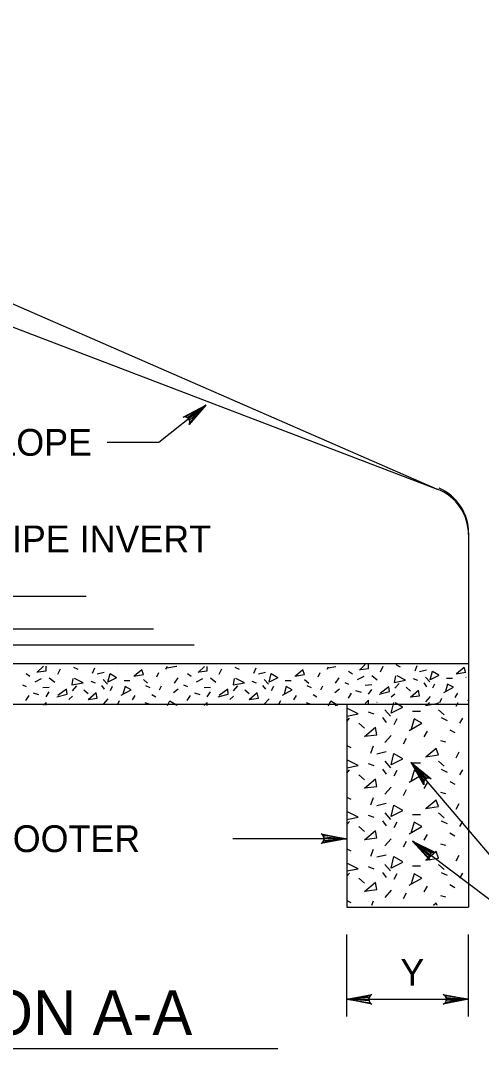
# Model space of a CAD drawing. Extents: x 1 to 8.2, y -2.1 to 8.1.
# Drawn here: x 3.034 to 4.066, y 2.836 to 5.137 of the extents above; entities that cross this region are included whole.
import ezdxf

# ---------------------------------------------------------------- set-up
doc = ezdxf.new("R2010")
doc.units = 0
for name, color, linetype in [('DETL-DIMS', 7, 'Continuous'), ('DETL-LINE', 7, 'Continuous'), ('DETL-NOTE', 7, 'Continuous'), ('DETL-PATT', 7, 'Continuous'), ('DETL-TITL', 7, 'Continuous')]:
    doc.layers.add(name, color=color, linetype=linetype)

msp = doc.modelspace()

# ---------------------------------------------------------------- linework, layer by layer
at = {"layer": 'DETL-DIMS'}
for p, q in [((3.4486, 4.2766), (3.3436, 4.1931)), ((3.3436, 4.1931), (3.2278, 4.1931)), ((4.3231, 2.9891), (3.9085, 3.4763)), ((3.763, 3.3059), (3.5089, 3.3059)), ((3.9112, 3.3004), (4.3231, 2.9891)), ((3.7642, 2.9079), (3.7642, 3.0918)), ((4.0369, 2.9079), (4.0369, 3.0918)), ((3.7642, 2.9464), (4.0369, 2.9464))]:
    msp.add_line(p, q, dxfattribs=at)
for points in [[(3.4486, 4.2766), (3.411, 4.2332), (3.4125, 4.2382), (3.4119, 4.2426), (3.4101, 4.246), (3.4072, 4.2485), (3.4031, 4.2501), (3.3978, 4.2498), (3.4486, 4.2766), (3.4031, 4.2501), (3.4072, 4.2485), (3.4486, 4.2766), (3.4101, 4.246), (3.4119, 4.2426), (3.4486, 4.2766), (3.4125, 4.2382)], [(3.9085, 3.4763), (3.9532, 3.4401), (3.9481, 3.4415), (3.9437, 3.4408), (3.9404, 3.4388), (3.9379, 3.4358), (3.9365, 3.4317), (3.937, 3.4264), (3.9085, 3.4763), (3.9365, 3.4317), (3.9379, 3.4358), (3.9085, 3.4763), (3.9404, 3.4388), (3.9437, 3.4408), (3.9085, 3.4763), (3.9481, 3.4415)], [(3.9085, 3.4763), (3.9532, 3.4401), (3.9481, 3.4415), (3.9437, 3.4408), (3.9404, 3.4388), (3.9379, 3.4358), (3.9365, 3.4317), (3.937, 3.4264), (3.9085, 3.4763), (3.9365, 3.4317), (3.9379, 3.4358), (3.9085, 3.4763), (3.9404, 3.4388), (3.9437, 3.4408), (3.9085, 3.4763), (3.9481, 3.4415)], [(3.763, 3.3059), (3.7065, 3.2954), (3.7108, 3.2984), (3.7131, 3.3022), (3.7137, 3.3059), (3.7131, 3.3097), (3.7108, 3.3135), (3.7065, 3.3165), (3.763, 3.3059), (3.7108, 3.3135), (3.7131, 3.3097), (3.763, 3.3059), (3.7137, 3.3059), (3.7131, 3.3022), (3.763, 3.3059), (3.7108, 3.2984)], [(3.9112, 3.3004), (3.9626, 3.2748), (3.9573, 3.275), (3.9533, 3.2733), (3.9505, 3.2707), (3.9487, 3.2673), (3.9482, 3.2629), (3.9499, 3.2579), (3.9112, 3.3004), (3.9482, 3.2629), (3.9487, 3.2673), (3.9112, 3.3004), (3.9505, 3.2707), (3.9533, 3.2733), (3.9112, 3.3004), (3.9573, 3.275)], [(3.7642, 2.9464), (3.8207, 2.9569), (3.8163, 2.9539), (3.8141, 2.9501), (3.8134, 2.9464), (3.8141, 2.9426), (3.8163, 2.9388), (3.8207, 2.9358), (3.7642, 2.9464), (3.8163, 2.9388), (3.8141, 2.9426), (3.7642, 2.9464), (3.8134, 2.9464), (3.8141, 2.9501), (3.7642, 2.9464), (3.8163, 2.9539)], [(4.0369, 2.9464), (3.9804, 2.9358), (3.9848, 2.9388), (3.987, 2.9426), (3.9877, 2.9464), (3.987, 2.9501), (3.9848, 2.9539), (3.9804, 2.9569), (4.0369, 2.9464), (3.9848, 2.9539), (3.987, 2.9501), (4.0369, 2.9464), (3.9877, 2.9464), (3.987, 2.9426), (4.0369, 2.9464), (3.9848, 2.9388)]]:
    msp.add_lwpolyline(points, dxfattribs=at)
at = {"layer": 'DETL-LINE'}
for p, q in [((1.5635, 5.1374), (3.9667, 4.0886)), ((2.3702, 4.6982), (3.9667, 4.0886)), ((4.0369, 3.9904), (4.0369, 3.6982)), ((1.5824, 3.8486), (3.1805, 3.8486)), ((1.5824, 3.7759), (3.3316, 3.7759)), ((1.5824, 3.7395), (3.4222, 3.7395)), ((1.6733, 3.6982), (4.0369, 3.6982)), ((4.0369, 3.6982), (4.0369, 3.1528)), ((1.5824, 3.6073), (4.0369, 3.6073)), ((3.7642, 3.6073), (3.7642, 3.1528)), ((3.7642, 3.1528), (4.0369, 3.1528))]:
    msp.add_line(p, q, dxfattribs=at)
for centre, end in [((3.9278, 3.9867), 69.1021), ((3.9278, 3.9904), 66.4251)]:
    msp.add_arc(centre, 0.1091, 0, end, dxfattribs=at)
at = {"layer": 'DETL-PATT'}
for p, q in [((3.0852, 3.6918), (3.0704, 3.6779)), ((3.1173, 3.6743), (3.1233, 3.6864)), ((3.1522, 3.69), (3.1619, 3.6852)), ((3.1992, 3.6876), (3.1943, 3.6755)), ((3.2499, 3.6915), (3.2497, 3.6912)), ((3.3592, 3.6852), (3.3625, 3.6912)), ((3.3832, 3.6912), (3.3616, 3.6876)), ((3.3832, 3.6912), (3.3832, 3.6912)), ((3.3832, 3.6912), (3.3832, 3.6912)), ((3.3832, 3.6912), (3.3832, 3.6912)), ((3.3832, 3.6912), (3.3832, 3.6912)), ((3.3832, 3.6912), (3.3832, 3.6912)), ((3.3832, 3.6912), (3.3832, 3.6912)), ((3.3832, 3.6912), (3.3832, 3.6912)), ((3.3832, 3.6912), (3.3832, 3.6912)), ((3.3832, 3.6912), (3.3832, 3.6912)), ((3.3832, 3.6912), (3.3832, 3.6912)), ((3.3832, 3.6912), (3.3832, 3.6912)), ((3.3832, 3.6912), (3.3832, 3.6912)), ((3.3833, 3.6912), (3.3832, 3.6912)), ((3.3833, 3.6912), (3.3833, 3.6912)), ((3.3833, 3.6912), (3.3833, 3.6912)), ((3.3833, 3.6912), (3.3833, 3.6912)), ((3.3833, 3.6912), (3.3833, 3.6912)), ((3.3833, 3.6912), (3.3833, 3.6912)), ((3.3833, 3.6912), (3.3833, 3.6912)), ((3.4453, 3.691), (3.4314, 3.6779)), ((3.4784, 3.6743), (3.4844, 3.6864)), ((3.5133, 3.69), (3.5229, 3.6852)), ((3.5602, 3.6876), (3.5554, 3.6755)), ((3.7203, 3.6852), (3.7231, 3.6904)), ((3.7395, 3.6904), (3.7227, 3.6876)), ((3.8055, 3.6957), (3.7925, 3.6834)), ((3.8394, 3.6798), (3.8454, 3.6919)), ((3.8743, 3.6955), (3.8839, 3.6906)), ((3.9212, 3.6931), (3.9164, 3.681)), ((3.9429, 3.6834), (3.9272, 3.6798)), ((3.0463, 3.6755), (3.0548, 3.6695)), ((3.08, 3.6635), (3.0656, 3.6563)), ((3.0981, 3.6659), (3.1101, 3.6563)), ((3.1907, 3.6587), (3.2004, 3.6551)), ((3.2208, 3.6779), (3.2052, 3.6743)), ((3.2184, 3.6623), (3.228, 3.6515)), ((3.2654, 3.6599), (3.2786, 3.6599)), ((3.3087, 3.6623), (3.3183, 3.6539)), ((3.3388, 3.6683), (3.3436, 3.6779)), ((3.3857, 3.6659), (3.3773, 3.6539)), ((3.4074, 3.6755), (3.4158, 3.6695)), ((3.4411, 3.6635), (3.4266, 3.6563)), ((3.4591, 3.6659), (3.4711, 3.6563)), ((3.5518, 3.6587), (3.5614, 3.6551)), ((3.5819, 3.6779), (3.5662, 3.6743)), ((3.5795, 3.6623), (3.5891, 3.6515)), ((3.6264, 3.6599), (3.6396, 3.6599)), ((3.6697, 3.6623), (3.6793, 3.6539)), ((3.6998, 3.6683), (3.7046, 3.6779)), ((3.7467, 3.6659), (3.7383, 3.6539)), ((3.7684, 3.681), (3.7768, 3.675)), ((3.8021, 3.669), (3.7876, 3.6618)), ((3.8201, 3.6714), (3.8322, 3.6618)), ((3.9128, 3.6642), (3.9224, 3.6606)), ((3.9405, 3.6678), (3.9501, 3.657)), ((3.9874, 3.6654), (4.0007, 3.6654)), ((4.0091, 3.675), (4.0305, 3.6786)), ((4.0307, 3.6678), (4.0316, 3.667)), ((3.0379, 3.6503), (3.0463, 3.6466)), ((3.0836, 3.6442), (3.0981, 3.6454)), ((3.1498, 3.637), (3.1595, 3.6479)), ((3.1751, 3.6394), (3.1847, 3.631)), ((3.2148, 3.6491), (3.2208, 3.6406)), ((3.2389, 3.6466), (3.2341, 3.637)), ((3.3135, 3.6491), (3.3231, 3.6442)), ((3.3448, 3.6394), (3.3496, 3.6479)), ((3.3869, 3.6406), (3.3761, 3.6322)), ((3.3989, 3.6503), (3.4074, 3.6466)), ((3.4447, 3.6442), (3.4591, 3.6454)), ((3.5109, 3.637), (3.5205, 3.6479)), ((3.5361, 3.6394), (3.5458, 3.631)), ((3.5758, 3.6491), (3.5819, 3.6406)), ((3.5999, 3.6466), (3.5951, 3.637)), ((3.6745, 3.6491), (3.6841, 3.6442)), ((3.7058, 3.6394), (3.7106, 3.6479)), ((3.7479, 3.6406), (3.7371, 3.6322)), ((3.76, 3.6557), (3.7684, 3.6521)), ((3.784, 3.6377), (3.7961, 3.6341)), ((3.8057, 3.6497), (3.8201, 3.6509)), ((3.8129, 3.6293), (3.8201, 3.6401)), ((3.8719, 3.6425), (3.8815, 3.6533)), ((3.8972, 3.6449), (3.9068, 3.6365)), ((3.9369, 3.6545), (3.9429, 3.6461)), ((3.9609, 3.6521), (3.9561, 3.6425)), ((3.0523, 3.6262), (3.0451, 3.6154)), ((3.062, 3.6322), (3.074, 3.6286)), ((3.0909, 3.6238), (3.0981, 3.6346)), ((3.1414, 3.6178), (3.1498, 3.625)), ((3.2292, 3.619), (3.2184, 3.6069)), ((3.2545, 3.6142), (3.2497, 3.6046)), ((3.2846, 3.6166), (3.2906, 3.6262)), ((3.3279, 3.6286), (3.3364, 3.6238)), ((3.4134, 3.6262), (3.4062, 3.6154)), ((3.423, 3.6322), (3.435, 3.6286)), ((3.4519, 3.6238), (3.4591, 3.6346)), ((3.5024, 3.6178), (3.5109, 3.625)), ((3.5903, 3.619), (3.5795, 3.6069)), ((3.6156, 3.6142), (3.6107, 3.6045)), ((3.6456, 3.6166), (3.6517, 3.6262)), ((3.689, 3.6286), (3.6974, 3.6238)), ((3.7744, 3.6317), (3.7672, 3.6208)), ((3.8635, 3.6233), (3.8719, 3.6305)), ((3.9513, 3.6245), (3.9405, 3.6124)), ((3.9766, 3.6196), (3.9718, 3.61)), ((4.0067, 3.6221), (4.0127, 3.6317)), ((4.0344, 3.616), (4.0363, 3.6155)), ((3.3123, 3.6105), (3.3207, 3.6081)), ((3.382, 3.6043), (3.3819, 3.6043)), ((3.3819, 3.6043), (3.3819, 3.6043)), ((3.3819, 3.6043), (3.3819, 3.6043)), ((3.3819, 3.6043), (3.3819, 3.6043)), ((3.3819, 3.6043), (3.3819, 3.6043)), ((3.3819, 3.6043), (3.3819, 3.6043)), ((3.3819, 3.6043), (3.3819, 3.6043)), ((3.3819, 3.6043), (3.3819, 3.6043)), ((3.3819, 3.6043), (3.3819, 3.6043)), ((3.3819, 3.6043), (3.3819, 3.6043)), ((3.3819, 3.6043), (3.3819, 3.6043)), ((3.3819, 3.6043), (3.3819, 3.6043)), ((3.3819, 3.6043), (3.3819, 3.6043)), ((3.3819, 3.6043), (3.3819, 3.6043)), ((3.3819, 3.6043), (3.3819, 3.6043)), ((3.3819, 3.6043), (3.3819, 3.6043)), ((3.3819, 3.6043), (3.3819, 3.6043)), ((3.3819, 3.6043), (3.3819, 3.6043)), ((3.3819, 3.6043), (3.3819, 3.6043)), ((3.3819, 3.6043), (3.3819, 3.6043)), ((3.3819, 3.6043), (3.3819, 3.6043)), ((3.3819, 3.6043), (3.3819, 3.6043)), ((3.3819, 3.6043), (3.3819, 3.6043)), ((3.3819, 3.6043), (3.3819, 3.6043)), ((3.3819, 3.6043), (3.3819, 3.6043)), ((3.3819, 3.6043), (3.3819, 3.6043)), ((3.3819, 3.6043), (3.3819, 3.6043)), ((3.3819, 3.6043), (3.3819, 3.6043)), ((3.3819, 3.6043), (3.3819, 3.6043)), ((3.3819, 3.6043), (3.3819, 3.6043)), ((3.3819, 3.6043), (3.3819, 3.6043)), ((3.3819, 3.6043), (3.3819, 3.6043)), ((3.3819, 3.6043), (3.3819, 3.6043)), ((3.3819, 3.6043), (3.3819, 3.6043)), ((3.3819, 3.6043), (3.3819, 3.6043)), ((3.3819, 3.6043), (3.3819, 3.6043)), ((3.3819, 3.6043), (3.3819, 3.6043)), ((3.3819, 3.6043), (3.3819, 3.6043)), ((3.3819, 3.6043), (3.3819, 3.6043)), ((3.3819, 3.6043), (3.3819, 3.6043)), ((3.3819, 3.6043), (3.3819, 3.6043)), ((3.3819, 3.6043), (3.3819, 3.6043)), ((3.3819, 3.6043), (3.3819, 3.6043)), ((3.3819, 3.6043), (3.3819, 3.6043)), ((3.3819, 3.6043), (3.3819, 3.6043)), ((3.3819, 3.6043), (3.3819, 3.6043)), ((3.3819, 3.6043), (3.3819, 3.6043)), ((3.3819, 3.6043), (3.3819, 3.6043)), ((3.3819, 3.6043), (3.3819, 3.6043)), ((3.3819, 3.6043), (3.3819, 3.6043)), ((3.3819, 3.6043), (3.3819, 3.6043)), ((3.3819, 3.6043), (3.3819, 3.6043)), ((3.3819, 3.6043), (3.3819, 3.6043)), ((3.3819, 3.6043), (3.3819, 3.6043)), ((3.3819, 3.6043), (3.3819, 3.6043)), ((3.3819, 3.6043), (3.3819, 3.6043)), ((3.3819, 3.6043), (3.3819, 3.6043)), ((3.3819, 3.6043), (3.3819, 3.6043)), ((3.3819, 3.6043), (3.3819, 3.6043)), ((3.3819, 3.6043), (3.3819, 3.6043)), ((3.3819, 3.6043), (3.3819, 3.6043)), ((3.3819, 3.6043), (3.3819, 3.6043)), ((3.3819, 3.6043), (3.3819, 3.6043)), ((3.3819, 3.6043), (3.3819, 3.6043)), ((3.3819, 3.6043), (3.3819, 3.6043)), ((3.3819, 3.6043), (3.3819, 3.6043)), ((3.3819, 3.6043), (3.3819, 3.6043)), ((3.3819, 3.6043), (3.3819, 3.6043)), ((3.3819, 3.6043), (3.3819, 3.6043)), ((3.3819, 3.6043), (3.3819, 3.6043)), ((3.382, 3.6043), (3.382, 3.6043)), ((3.382, 3.6043), (3.382, 3.6043)), ((3.382, 3.6043), (3.382, 3.6043)), ((3.382, 3.6043), (3.382, 3.6043)), ((3.6733, 3.6105), (3.6817, 3.6081)), ((3.7384, 3.6035), (3.7383, 3.6035)), ((3.7383, 3.6035), (3.7383, 3.6035)), ((3.7383, 3.6035), (3.7383, 3.6035)), ((3.7383, 3.6035), (3.7383, 3.6035)), ((3.7383, 3.6035), (3.7383, 3.6035)), ((3.7383, 3.6035), (3.7383, 3.6035)), ((3.7383, 3.6035), (3.7383, 3.6035)), ((3.7383, 3.6035), (3.7383, 3.6035)), ((3.7383, 3.6035), (3.7383, 3.6035)), ((3.7383, 3.6035), (3.7383, 3.6035)), ((3.7383, 3.6035), (3.7383, 3.6035)), ((3.7383, 3.6035), (3.7383, 3.6035)), ((3.7383, 3.6035), (3.7383, 3.6035)), ((3.7383, 3.6035), (3.7383, 3.6035)), ((3.7383, 3.6035), (3.7383, 3.6035)), ((3.7383, 3.6035), (3.7383, 3.6035)), ((3.7383, 3.6035), (3.7383, 3.6035)), ((3.7383, 3.6035), (3.7383, 3.6035)), ((3.7383, 3.6035), (3.7383, 3.6035)), ((3.7383, 3.6035), (3.7383, 3.6035)), ((3.7383, 3.6035), (3.7383, 3.6035)), ((3.7383, 3.6035), (3.7383, 3.6035)), ((3.7383, 3.6035), (3.7383, 3.6035)), ((3.7383, 3.6035), (3.7383, 3.6035)), ((3.7383, 3.6035), (3.7383, 3.6035)), ((3.7383, 3.6035), (3.7383, 3.6035)), ((3.7383, 3.6035), (3.7383, 3.6035)), ((3.7383, 3.6035), (3.7383, 3.6035)), ((3.7383, 3.6035), (3.7383, 3.6035)), ((3.7383, 3.6035), (3.7383, 3.6035)), ((3.7383, 3.6035), (3.7383, 3.6035)), ((3.7383, 3.6035), (3.7383, 3.6035)), ((3.7383, 3.6035), (3.7383, 3.6035)), ((3.7383, 3.6035), (3.7383, 3.6035)), ((3.7383, 3.6035), (3.7383, 3.6035)), ((3.7383, 3.6035), (3.7383, 3.6035)), ((3.7383, 3.6035), (3.7383, 3.6035)), ((3.7383, 3.6035), (3.7383, 3.6035)), ((3.7383, 3.6035), (3.7383, 3.6035)), ((3.7383, 3.6035), (3.7383, 3.6035)), ((3.7383, 3.6035), (3.7383, 3.6035)), ((3.7383, 3.6035), (3.7383, 3.6035)), ((3.7383, 3.6035), (3.7383, 3.6035)), ((3.7383, 3.6035), (3.7383, 3.6035)), ((3.7383, 3.6035), (3.7383, 3.6035)), ((3.7383, 3.6035), (3.7383, 3.6035)), ((3.7383, 3.6035), (3.7383, 3.6035)), ((3.7383, 3.6035), (3.7383, 3.6035)), ((3.7383, 3.6035), (3.7383, 3.6035)), ((3.7383, 3.6035), (3.7383, 3.6035)), ((3.7383, 3.6035), (3.7383, 3.6035)), ((3.7383, 3.6035), (3.7383, 3.6035)), ((3.7383, 3.6035), (3.7383, 3.6035)), ((3.7383, 3.6035), (3.7383, 3.6035)), ((3.7383, 3.6035), (3.7383, 3.6035)), ((3.7383, 3.6035), (3.7383, 3.6035)), ((3.7383, 3.6035), (3.7383, 3.6035)), ((3.7383, 3.6035), (3.7383, 3.6035)), ((3.7383, 3.6035), (3.7383, 3.6035)), ((3.7384, 3.6035), (3.7384, 3.6035)), ((3.7384, 3.6035), (3.7384, 3.6035)), ((3.7384, 3.6035), (3.7384, 3.6035)), ((3.7384, 3.6035), (3.7384, 3.6035)), ((3.7384, 3.6035), (3.7384, 3.6035)), ((3.7384, 3.6035), (3.7384, 3.6035)), ((3.7384, 3.6035), (3.7384, 3.6035)), ((3.7384, 3.6035), (3.7384, 3.6035)), ((3.7384, 3.6035), (3.7384, 3.6035)), ((3.7384, 3.6035), (3.7384, 3.6035)), ((3.7384, 3.6035), (3.7384, 3.6035)), ((3.7384, 3.6035), (3.7384, 3.6035)), ((3.7384, 3.6035), (3.7384, 3.6035)), ((3.7384, 3.6035), (3.7384, 3.6035)), ((3.7384, 3.6035), (3.7384, 3.6035)), ((3.7384, 3.6035), (3.7384, 3.6035)), ((3.7384, 3.6035), (3.7384, 3.6035)), ((3.7384, 3.6035), (3.7384, 3.6035)), ((3.7384, 3.6035), (3.7384, 3.6035)), ((3.7384, 3.6035), (3.7384, 3.6035)), ((3.7384, 3.6035), (3.7384, 3.6035)), ((3.8122, 3.5899), (3.825, 3.5851)), ((3.8321, 3.6109), (3.8314, 3.6108)), ((3.8491, 3.5947), (3.8619, 3.5803)), ((3.8724, 3.6109), (3.8892, 3.6011)), ((3.8743, 3.6088), (3.8744, 3.6087)), ((3.9116, 3.5915), (3.9293, 3.5915)), ((3.9498, 3.6109), (3.9421, 3.6043)), ((3.9694, 3.5947), (3.9822, 3.5835)), ((4.0095, 3.6027), (4.0136, 3.6109)), ((3.7642, 3.5684), (3.7704, 3.5755)), ((3.8442, 3.5771), (3.8523, 3.5658)), ((3.8763, 3.5739), (3.8699, 3.561)), ((3.9758, 3.5771), (3.9887, 3.5706)), ((4.0175, 3.5642), (4.024, 3.5755)), ((3.7913, 3.5642), (3.8041, 3.553)), ((3.9373, 3.5337), (3.9453, 3.5466)), ((3.9951, 3.5498), (4.0063, 3.5434)), ((3.8635, 3.537), (3.8491, 3.5209)), ((3.8972, 3.5305), (3.8908, 3.5177)), ((3.9742, 3.5257), (3.9854, 3.5225)), ((3.7642, 3.5144), (3.7736, 3.5097)), ((3.8234, 3.5129), (3.817, 3.4968)), ((3.8523, 3.5), (3.8314, 3.4952)), ((4.0095, 3.4872), (4.0159, 3.5)), ((4.0368, 3.5097), (4.0369, 3.5099)), ((3.8491, 3.4792), (3.8619, 3.4647)), ((3.9116, 3.476), (3.9293, 3.476)), ((3.9694, 3.4792), (3.9822, 3.468)), ((3.7642, 3.4529), (3.7704, 3.4599)), ((3.8122, 3.4744), (3.825, 3.4696)), ((3.8442, 3.4615), (3.8523, 3.4503)), ((3.8763, 3.4583), (3.8699, 3.4455)), ((3.9758, 3.4615), (3.9887, 3.4551)), ((4.0175, 3.4487), (4.024, 3.4599)), ((3.7913, 3.4487), (3.8041, 3.4375)), ((3.9373, 3.4182), (3.9453, 3.431)), ((3.9951, 3.4343), (4.0063, 3.4278)), ((3.8635, 3.4214), (3.8491, 3.4054)), ((3.8972, 3.415), (3.8908, 3.4022)), ((3.9742, 3.4102), (3.9854, 3.407)), ((3.7642, 3.3989), (3.7736, 3.3941)), ((3.8234, 3.3974), (3.817, 3.3813)), ((3.8523, 3.3845), (3.8314, 3.3797)), ((4.0095, 3.3717), (4.0159, 3.3845)), ((4.0368, 3.3941), (4.0369, 3.3944)), ((3.8491, 3.3637), (3.8619, 3.3492)), ((3.9116, 3.3604), (3.9293, 3.3604)), ((3.9694, 3.3637), (3.9822, 3.3524)), ((3.7642, 3.3374), (3.7704, 3.3444)), ((3.8122, 3.3588), (3.825, 3.354)), ((3.8442, 3.346), (3.8523, 3.3348)), ((3.8763, 3.3428), (3.8699, 3.33)), ((3.9758, 3.346), (3.9887, 3.3396)), ((4.0175, 3.3332), (4.024, 3.3444)), ((3.7913, 3.3332), (3.8041, 3.3219)), ((3.9373, 3.3027), (3.9453, 3.3155)), ((3.9951, 3.3187), (4.0063, 3.3123)), ((3.8635, 3.3059), (3.8491, 3.2898)), ((3.8972, 3.2995), (3.8908, 3.2866)), ((3.9742, 3.2947), (3.9854, 3.2915)), ((3.7642, 3.2833), (3.7736, 3.2786)), ((3.8234, 3.2818), (3.817, 3.2658)), ((3.8523, 3.269), (3.8314, 3.2642)), ((4.0095, 3.2561), (4.0159, 3.269)), ((4.0368, 3.2786), (4.0369, 3.2788)), ((3.8491, 3.2481), (3.8619, 3.2337)), ((3.9116, 3.2449), (3.9293, 3.2449)), ((3.9694, 3.2481), (3.9822, 3.2369)), ((3.7642, 3.2218), (3.7704, 3.2289)), ((3.8122, 3.2433), (3.825, 3.2385)), ((3.8442, 3.2305), (3.8523, 3.2192)), ((3.8763, 3.2273), (3.8699, 3.2144)), ((3.9758, 3.2305), (3.9887, 3.2241)), ((4.0175, 3.2176), (4.024, 3.2289)), ((3.7913, 3.2176), (3.8041, 3.2064)), ((3.9373, 3.1872), (3.9453, 3.2)), ((3.9951, 3.2032), (4.0063, 3.1968)), ((3.8635, 3.1904), (3.8491, 3.1743)), ((3.8972, 3.1839), (3.8908, 3.1711)), ((3.9742, 3.1791), (3.9854, 3.1759)), ((3.7642, 3.1678), (3.7736, 3.1631)), ((3.8234, 3.1663), (3.8194, 3.1564)), ((4.0368, 3.1631), (4.0369, 3.1633))]:
    msp.add_line(p, q, dxfattribs=at)
for points in [[(3.0728, 3.6791), (3.0909, 3.6815), (3.0909, 3.6918)], [(3.287, 3.6695), (3.3087, 3.6731), (3.3051, 3.684), (3.2882, 3.6695)], [(3.4338, 3.6791), (3.4519, 3.6815), (3.4519, 3.691)], [(3.648, 3.6695), (3.6697, 3.6731), (3.6661, 3.684), (3.6492, 3.6695)], [(3.7949, 3.6846), (3.8129, 3.687), (3.8129, 3.6957)], [(4.0304, 3.6795), (4.0271, 3.6894), (4.0103, 3.675)], [(3.151, 3.6647), (3.1486, 3.6503), (3.1739, 3.6551), (3.1546, 3.6647)], [(3.2485, 3.6659), (3.2292, 3.6563), (3.2341, 3.6755), (3.2485, 3.6671)], [(3.5121, 3.6647), (3.5097, 3.6503), (3.5349, 3.6551), (3.5157, 3.6647)], [(3.6095, 3.6659), (3.5903, 3.6563), (3.5951, 3.6755), (3.6095, 3.6671)], [(3.8731, 3.6702), (3.8707, 3.6557), (3.896, 3.6606), (3.8767, 3.6702)], [(3.9706, 3.6714), (3.9513, 3.6618), (3.9561, 3.681), (3.9706, 3.6726)], [(3.1149, 3.6238), (3.1378, 3.6298), (3.1366, 3.6406), (3.1173, 3.6262)], [(3.2593, 3.6274), (3.281, 3.6394), (3.2678, 3.6466), (3.2629, 3.6298)], [(3.476, 3.6238), (3.4988, 3.6298), (3.4976, 3.6406), (3.4784, 3.6262)], [(3.6204, 3.6274), (3.642, 3.6394), (3.6288, 3.6466), (3.624, 3.6298)], [(3.837, 3.6293), (3.8599, 3.6353), (3.8586, 3.6461), (3.8394, 3.6317)], [(3.9068, 3.6233), (3.9272, 3.6257), (3.9248, 3.6377), (3.9068, 3.6221)], [(3.9814, 3.6329), (4.0031, 3.6449), (3.9898, 3.6521), (3.985, 3.6353)], [(3.1847, 3.6178), (3.2052, 3.6202), (3.2028, 3.6322), (3.1847, 3.6166)], [(3.3624, 3.6043), (3.3676, 3.6142), (3.3833, 3.6045), (3.382, 3.6043)], [(3.5458, 3.6178), (3.5662, 3.6202), (3.5638, 3.6322), (3.5458, 3.6166)], [(3.723, 3.6036), (3.7287, 3.6142), (3.7443, 3.6045), (3.7384, 3.6035)], [(3.8129, 3.6089), (3.8129, 3.616), (3.8053, 3.6089)], [(3.0909, 3.6049), (3.0909, 3.6105), (3.0849, 3.6049)], [(3.4519, 3.6042), (3.4519, 3.6105), (3.4451, 3.6042)], [(3.7642, 3.5802), (3.7897, 3.5851), (3.7642, 3.5978)], [(3.8892, 3.5995), (3.8635, 3.5867), (3.8696, 3.6109)], [(3.9405, 3.6043), (3.9694, 3.6092), (3.9688, 3.6109)], [(3.9036, 3.5482), (3.9325, 3.5642), (3.9148, 3.5739), (3.9084, 3.5514)], [(3.8041, 3.5353), (3.8314, 3.5386), (3.8282, 3.5546), (3.8041, 3.5337)], [(3.9405, 3.4888), (3.9694, 3.4936), (3.9646, 3.5081), (3.9421, 3.4888)], [(3.7642, 3.4647), (3.7897, 3.4696), (3.7642, 3.4823)], [(3.8892, 3.484), (3.8635, 3.4712), (3.8699, 3.4968), (3.8892, 3.4856)], [(3.9036, 3.4327), (3.9325, 3.4487), (3.9148, 3.4583), (3.9084, 3.4359)], [(3.8041, 3.4198), (3.8314, 3.423), (3.8282, 3.4391), (3.8041, 3.4182)], [(3.9405, 3.3733), (3.9694, 3.3781), (3.9646, 3.3925), (3.9421, 3.3733)], [(3.7642, 3.3492), (3.7897, 3.354), (3.7642, 3.3668)], [(3.8892, 3.3685), (3.8635, 3.3556), (3.8699, 3.3813), (3.8892, 3.3701)], [(3.9036, 3.3171), (3.9325, 3.3332), (3.9148, 3.3428), (3.9084, 3.3203)], [(3.8041, 3.3043), (3.8314, 3.3075), (3.8282, 3.3235), (3.8041, 3.3027)], [(3.9405, 3.2578), (3.9694, 3.2626), (3.9646, 3.277), (3.9421, 3.2578)], [(3.7642, 3.2336), (3.7897, 3.2385), (3.7642, 3.2513)], [(3.8892, 3.2529), (3.8635, 3.2401), (3.8699, 3.2658), (3.8892, 3.2545)], [(3.9036, 3.2016), (3.9325, 3.2176), (3.9148, 3.2273), (3.9084, 3.2048)], [(3.8041, 3.1888), (3.8314, 3.192), (3.8282, 3.208), (3.8041, 3.1872)], [(3.9663, 3.1564), (3.9646, 3.1615), (3.9586, 3.1564)]]:
    msp.add_lwpolyline(points, dxfattribs=at)
at = {"layer": 'DETL-TITL'}
msp.add_line((2.5635, 2.8364), (3.6096, 2.8364), dxfattribs=at)

# ---------------------------------------------------------------- texts
at = {"layer": 'DETL-NOTE'}
for s, p in [('SLOPE', (2.926, 4.1631)), ('SAME GRADE AS PIPE INVERT', (2.2743, 3.947)), ('OPTIONAL CONCRETE FOOTER', (2.0667, 3.2759)), ('Y', (3.8842, 2.9767))]:
    msp.add_text(s, height=0.06, dxfattribs=at).set_placement(p)
at = {"layer": 'DETL-TITL'}
msp.add_text('SECTION A-A', height=0.1, dxfattribs=at).set_placement((2.5637, 2.8667))

doc.saveas('drawing.dxf')
